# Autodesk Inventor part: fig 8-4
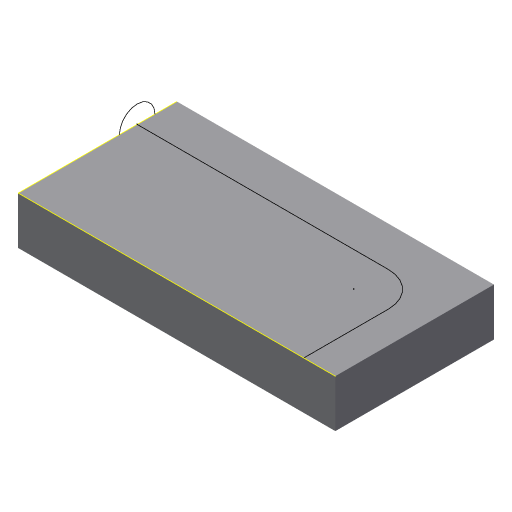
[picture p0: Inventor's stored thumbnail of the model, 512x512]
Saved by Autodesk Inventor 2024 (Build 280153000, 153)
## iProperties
Created: 2009-04
Part Number: fig 8-4
Document SubType Name: Modeling
Designer: Sham
Density: 1 g/cm^3
Material: Generic
Appearance: Default
Author: Sham
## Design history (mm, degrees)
sketch "Sketch1"
  geometry: L1 (-20, 20)-(20, 20); L2 (20, 20)-(20, 0); L3 (20, 0)-(-20, 0); L4 (-20, 0)-(-20, 20)
  constraints: 8 end point
extrude "Extrusion1" new body sketch "Sketch1" distance "d0" = 6; taper "d1" = 0 deg
sketch "Sketch4"
  geometry: L1 (6, 0)-(6, 20) reference; C1 r 2.236 at (6, 15)
  constraints: 1 centre point, 1 point on line
sketch "Sketch5"
  geometry: L1 (-20, 0)-(-20, 20) reference; L2 (20, 0)-(-20, 0) reference; L3 (-20, 15)-(11.667, 15); L4 (16, 10.667)-(16, 0); A1 r 4.333 centre (11.667, 10.667) between (16, 10.667) and (11.667, 15)
  constraints: 4 end point, 2 point on circle, 2 point on line, 1 centre point, 1 tangent
body "Solid1"
